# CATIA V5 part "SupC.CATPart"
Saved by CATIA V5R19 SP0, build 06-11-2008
Part number: SupC
Publications: "Li", "H", "e", "La"
Bounding box of the stored display mesh (mm): x -40 to 0, y -10 to 120, z 0 to 150
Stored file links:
  G:\EU_thinkMotion\CFAO_2010\MMS_groupe3\MMS_groupe3\A reprendre\evulliez\evulliez\SupC.CATPart
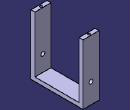
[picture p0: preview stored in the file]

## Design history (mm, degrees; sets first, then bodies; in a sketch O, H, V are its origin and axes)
Parameters
  Li = 110 mm
  H = 150 mm
  e = 10 mm
  La = 40 mm
Body1 (main body)
  Sketch1 on zx-plane, origin (0, 0, 0), H (-1, 0, 0), V (0, 0, 1)
    line L1 (0, 0) -> (40, 0)
    line L2 (40, 0) -> (40, 150)
    line L3 (40, 150) -> (0, 150)
    line L4 (0, 150) -> (0, 0)
    length L1 = 40 {= La}
    length L2 = 150 {= H}
    horizontal: L1 H, L3 H
    vertical: L2 V, L4 V
  Pad1: profile Sketch1, direction (0, -1, 0), length 10 {= e}
  Sketch2 on start face of Pad1, origin (0, 0, 0), H (-1, 0, 0), V (0, 0, 1)
    line L1 (0, 0) -> (40, 0)
    line L2 (40, 0) -> (40, 10)
    line L3 (40, 10) -> (0, 10)
    line L4 (0, 10) -> (0, 0)
    length L2 = 10 {= e}
    length L1 = 40 {= La}
    horizontal: L1 H, L3 H
    vertical: L2 V, L4 V
  Pad2: profile Sketch2, direction (0, 1, 0), length 55 {= Li /2}
  Mirror1: of Pad1, Pad2, about end face of Pad2
  Point1: type OnPlane, Support face of Pad1 from Sketch1.L3, H -20 {= -La /2}, V -5 {= -e /2}, Direction (1, 0, 0)
  Point2: type OnPlane, Support face of Mirror1, H -20 {= -La /2}, V 115 {= Li +e /2}, Direction (1, 0, 0)
  Sketch3 on face of Pad1 from Sketch1.L3, origin (-20, -5, 150), H (1, 0, 0), V (0, 1, 0)
    point P1 (0, 0)
    reference projected point E1 (0, 0) from Point1
    coincidence: E1 P1
  Hole1: placed by Sketch3, at (-20, -5, 150) direction (0, 0, -1), diameter 6, depth 8
  Sketch4 on face of Mirror1, origin (-20, 95, 150), H (1, 0, 0), V (0, 1, 0)
    point P1 (0, 20)
    reference projected point E1 (0, 20) from Point2
    coincidence: E1 P1
  Hole2: placed by Sketch4, at (-20, 115, 150) direction (0, 0, -1), diameter 6, depth 8
  Point3: type OnPlane, Support end face of Pad1, H -20 {= -La /2}, V 50, Direction (1, 0, 0)
  Sketch5 on end face of Pad1, origin (-20, -10, 40), H (1, 0, 0), V (0, 0, 1)
    point P1 (0, 10)
    reference projected point E1 (0, 10) from Point3
    coincidence: E1 P1
  Hole3: placed by Sketch5, at (-20, -10, 50) direction (0, 1, 0), diameter 10, through (limit type 3)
